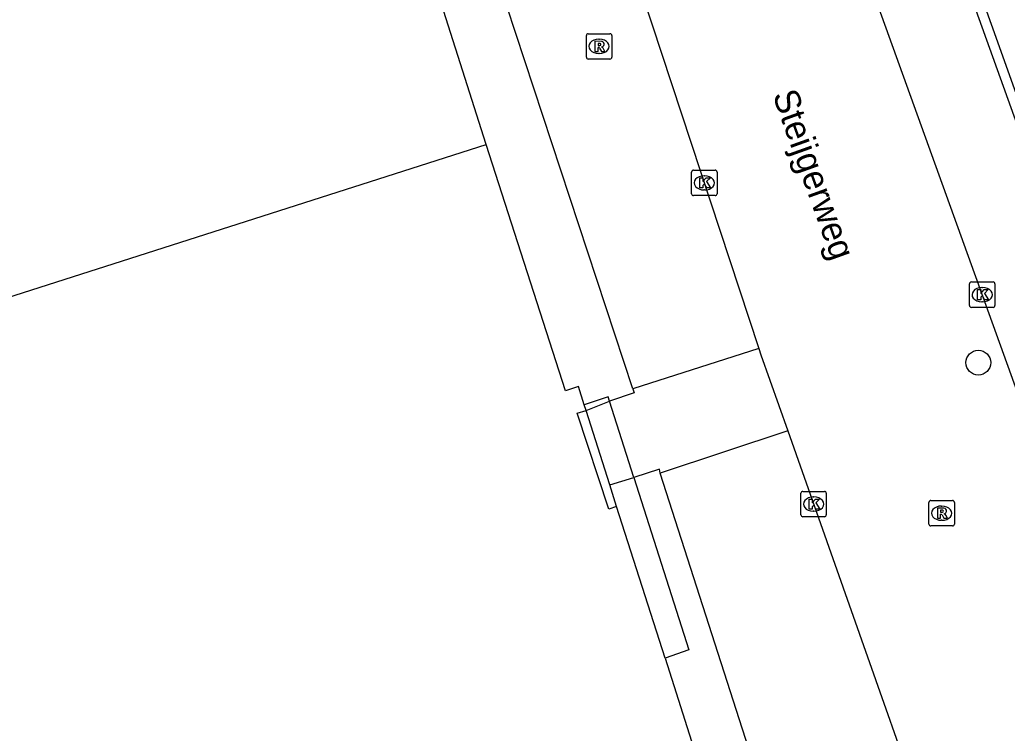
# Model space of a CAD drawing. Extents: x 159503 to 160347, y 382525 to 383272.
# Drawn here: x 159552.91 to 159591.78, y 382930.55 to 382958.63 of the extents above; entities that cross this region are included whole.
import ezdxf

# ---------------------------------------------------------------- set-up
doc = ezdxf.new("R2010")
doc.units = 0
for name, color, linetype in [('IMGEO_Boom', 7, 'Continuous'), ('IMGEO_Kolk', 7, 'Continuous'), ('IMGEO_Openbare_ruimte_label', 7, 'Continuous'), ('IMGEO_Pand', 7, 'Continuous'), ('IMGEO_Rijbaan_lokaal_open', 7, 'Continuous'), ('IMGEO_Rioolput', 7, 'Continuous'), ('IMGEO_Voetpad_open', 7, 'Continuous')]:
    doc.layers.add(name, color=color, linetype=linetype)

msp = doc.modelspace()

# ---------------------------------------------------------------- linework, layer by layer
at = {"layer": 'IMGEO_Boom'}
msp.add_circle((159590.637, 382945.135), 0.489, dxfattribs=at)
at = {"layer": 'IMGEO_Kolk'}
for p, q in [((159579.353, 382951.785), (159579.353, 382952.637)), ((159579.428, 382952.711), (159580.28, 382952.711)), ((159579.841, 382952.491), (159579.866, 382952.491)), ((159580.354, 382952.637), (159580.354, 382951.785)), ((159580.28, 382951.711), (159579.428, 382951.711)), ((159579.864, 382951.931), (159579.839, 382951.931)), ((159590.289, 382947.385), (159590.289, 382948.237)), ((159590.364, 382948.311), (159591.216, 382948.311)), ((159591.29, 382948.237), (159591.29, 382947.385)), ((159590.777, 382948.091), (159590.802, 382948.091)), ((159590.8, 382947.531), (159590.775, 382947.531)), ((159591.216, 382947.311), (159590.364, 382947.311)), ((159583.729, 382940.068), (159584.581, 382940.068)), ((159583.654, 382939.142), (159583.654, 382939.994)), ((159584.142, 382939.848), (159584.167, 382939.848)), ((159584.655, 382939.994), (159584.655, 382939.142)), ((159584.165, 382939.288), (159584.14, 382939.288)), ((159584.581, 382939.068), (159583.729, 382939.068))]:
    msp.add_line(p, q, dxfattribs=at)
for points in [[(159579.353, 382951.785), (159579.353, 382952.637)], [(159579.428, 382952.711), (159580.28, 382952.711)], [(159580.354, 382952.637), (159580.354, 382951.785)], [(159579.674, 382952.411), (159579.797, 382952.411), (159579.797, 382952.26), (159579.927, 382952.411), (159580.091, 382952.411), (159579.945, 382952.26), (159580.098, 382952.011), (159579.946, 382952.011), (159579.861, 382952.175), (159579.797, 382952.108), (159579.797, 382952.011), (159579.674, 382952.011), (159579.674, 382952.411)], [(159580.28, 382951.711), (159579.428, 382951.711)], [(159590.289, 382947.385), (159590.289, 382948.237)], [(159590.364, 382948.311), (159591.216, 382948.311)], [(159591.29, 382948.237), (159591.29, 382947.385)], [(159590.61, 382948.011), (159590.733, 382948.011), (159590.733, 382947.86), (159590.863, 382948.011), (159591.027, 382948.011), (159590.881, 382947.86), (159591.034, 382947.611), (159590.882, 382947.611), (159590.797, 382947.775), (159590.733, 382947.708), (159590.733, 382947.611), (159590.61, 382947.611), (159590.61, 382948.011)], [(159591.216, 382947.311), (159590.364, 382947.311)], [(159583.729, 382940.068), (159584.581, 382940.068)], [(159583.654, 382939.142), (159583.654, 382939.994)], [(159583.975, 382939.768), (159584.098, 382939.768), (159584.098, 382939.617), (159584.228, 382939.768), (159584.392, 382939.768), (159584.246, 382939.617), (159584.399, 382939.368), (159584.247, 382939.368), (159584.162, 382939.532), (159584.098, 382939.465), (159584.098, 382939.368), (159583.975, 382939.368), (159583.975, 382939.768)], [(159584.655, 382939.994), (159584.655, 382939.142)], [(159584.581, 382939.068), (159583.729, 382939.068)]]:
    msp.add_lwpolyline(points, dxfattribs=at)
for centre, start, end in [((159579.43, 382952.635), 91.552, 178.448), ((159579.43, 382952.635), 91.552, 178.448), ((159580.278, 382952.635), 1.552, 88.448), ((159580.278, 382952.635), 1.552, 88.448), ((159579.43, 382951.787), 181.552, 268.448), ((159579.43, 382951.787), 181.552, 268.448), ((159580.278, 382951.787), 271.552, 358.448), ((159580.278, 382951.787), 271.552, 358.448), ((159590.366, 382948.235), 91.552, 178.448), ((159590.366, 382948.235), 91.552, 178.448), ((159591.214, 382948.235), 1.552, 88.448), ((159591.214, 382948.235), 1.552, 88.448), ((159590.366, 382947.387), 181.552, 268.448), ((159590.366, 382947.387), 181.552, 268.448), ((159591.214, 382947.387), 271.552, 358.448), ((159591.214, 382947.387), 271.552, 358.448), ((159583.731, 382939.992), 91.552, 178.448), ((159583.731, 382939.992), 91.552, 178.448), ((159584.579, 382939.992), 1.552, 88.448), ((159584.579, 382939.992), 1.552, 88.448), ((159583.731, 382939.144), 181.552, 268.448), ((159583.731, 382939.144), 181.552, 268.448), ((159584.579, 382939.144), 271.552, 358.448), ((159584.579, 382939.144), 271.552, 358.448)]:
    msp.add_arc(centre, 0.0765, start, end, dxfattribs=at)
for centre, major_axis, ratio, start_param, end_param in [((159579.84, 382952.211), (-0.387, 0.002), 0.722429, 4.712389, 7.853982), ((159579.865, 382952.211), (-0.39, 0.002), 0.717154, 1.570796, 4.712389), ((159590.776, 382947.811), (-0.387, 0.002), 0.722429, 4.712389, 7.853982), ((159590.801, 382947.811), (-0.39, 0.002), 0.717154, 1.570796, 4.712389), ((159584.141, 382939.568), (-0.387, 0.002), 0.722429, 4.712389, 7.853982), ((159584.166, 382939.568), (-0.39, 0.002), 0.717154, 1.570796, 4.712389)]:
    msp.add_ellipse(centre, major_axis=major_axis, ratio=ratio, start_param=start_param, end_param=end_param, dxfattribs=at)
at = {"layer": 'IMGEO_Pand'}
for points in [[(159587.852, 382966.52), (159588.22, 382966.653), (159594.075, 382950.274)], [(159571.265, 382953.723), (159568.852, 382961.323)], [(159545.874, 382945.595), (159571.265, 382953.723)], [(159575.129, 382943.477), (159574.901, 382944.198), (159574.389, 382944.03), (159571.265, 382953.723)], [(159576.401, 382939.467), (159576.097, 382939.369), (159574.851, 382943.147), (159575.2, 382943.254)], [(159575.2, 382943.254), (159575.129, 382943.477)], [(159578.31, 382933.501), (159576.401, 382939.467)], [(159578.31, 382933.501), (159579.526, 382929.703), (159579.035, 382929.541), (159582.89, 382917.624)]]:
    msp.add_lwpolyline(points, dxfattribs=at)
at = {"layer": 'IMGEO_Rijbaan_lokaal_open'}
for points in [[(159575.122, 382966.572), (159582.001, 382945.695)], [(159584.573, 382965.063), (159592.904, 382941.945)], [(159582.001, 382945.695), (159582.084, 382945.442), (159583.137, 382942.457)], [(159583.137, 382942.457), (159591.263, 382919.413)]]:
    msp.add_lwpolyline(points, dxfattribs=at)
at = {"layer": 'IMGEO_Rioolput'}
for p, q in [((159575.212, 382957.157), (159575.212, 382958.009)), ((159575.287, 382958.083), (159576.139, 382958.083)), ((159576.213, 382958.009), (159576.213, 382957.157)), ((159575.7, 382957.863), (159575.725, 382957.863)), ((159575.723, 382957.303), (159575.698, 382957.303)), ((159576.139, 382957.083), (159575.287, 382957.083)), ((159588.693, 382938.784), (159588.693, 382939.636)), ((159588.768, 382939.71), (159589.62, 382939.71)), ((159589.694, 382939.636), (159589.694, 382938.784)), ((159589.181, 382939.49), (159589.206, 382939.49)), ((159589.204, 382938.93), (159589.179, 382938.93)), ((159589.62, 382938.71), (159588.768, 382938.71))]:
    msp.add_line(p, q, dxfattribs=at)
for points in [[(159575.212, 382957.157), (159575.212, 382958.009)], [(159575.287, 382958.083), (159576.139, 382958.083)], [(159576.213, 382958.009), (159576.213, 382957.157)], [(159575.801, 382957.781), (159575.549, 382957.783), (159575.549, 382957.383)], [(159575.549, 382957.383), (159575.673, 382957.383), (159575.673, 382957.545), (159575.684, 382957.545)], [(159575.727, 382957.702), (159575.673, 382957.702), (159575.673, 382957.621)], [(159575.673, 382957.621), (159575.725, 382957.621)], [(159575.731, 382957.516), (159575.802, 382957.383), (159575.942, 382957.383), (159575.877, 382957.509)], [(159576.139, 382957.083), (159575.287, 382957.083)], [(159588.693, 382938.784), (159588.693, 382939.636)], [(159588.768, 382939.71), (159589.62, 382939.71)], [(159589.694, 382939.636), (159589.694, 382938.784)], [(159589.282, 382939.408), (159589.03, 382939.41), (159589.03, 382939.01)], [(159589.208, 382939.329), (159589.154, 382939.329), (159589.154, 382939.248)], [(159589.154, 382939.248), (159589.206, 382939.248)], [(159589.03, 382939.01), (159589.154, 382939.01), (159589.154, 382939.172), (159589.165, 382939.172)], [(159589.212, 382939.143), (159589.283, 382939.01), (159589.423, 382939.01), (159589.358, 382939.136)], [(159589.62, 382938.71), (159588.768, 382938.71)]]:
    msp.add_lwpolyline(points, dxfattribs=at)
for centre, radius, start, end in [((159575.289, 382958.007), 0.0765, 91.552, 178.448), ((159575.289, 382958.007), 0.0765, 91.552, 178.448), ((159576.137, 382958.007), 0.0765, 1.552, 88.448), ((159576.137, 382958.007), 0.0765, 1.552, 88.448), ((159575.683, 382957.492), 0.0533, 26.0293, 88.6989), ((159575.709, 382957.81), 0.19, 274.7715, 282.9687), ((159575.733, 382957.606), 0.0964, 77.0061, 93.1865), ((159575.747, 382957.663), 0.0378, 276.6634, 79.6772), ((159575.8, 382957.671), 0.109, 350.3612, 89.416), ((159575.798, 382957.671), 0.112, 277.5842, 350.9817), ((159575.782, 382957.456), 0.108, 29.5134, 73.7905), ((159575.289, 382957.159), 0.0765, 181.552, 268.448), ((159575.289, 382957.159), 0.0765, 181.552, 268.448), ((159576.137, 382957.159), 0.0765, 271.552, 358.448), ((159576.137, 382957.159), 0.0765, 271.552, 358.448), ((159588.77, 382939.634), 0.0765, 91.552, 178.448), ((159588.77, 382939.634), 0.0765, 91.552, 178.448), ((159589.618, 382939.634), 0.0765, 1.552, 88.448), ((159589.618, 382939.634), 0.0765, 1.552, 88.448), ((159589.19, 382939.437), 0.19, 274.7715, 282.9687), ((159589.214, 382939.233), 0.0964, 77.0061, 93.1865), ((159589.228, 382939.29), 0.0378, 276.6634, 79.6772), ((159589.281, 382939.298), 0.109, 350.3612, 89.416), ((159589.279, 382939.298), 0.112, 277.5842, 350.9817), ((159589.164, 382939.119), 0.0533, 26.0293, 88.6989), ((159589.263, 382939.083), 0.108, 29.5134, 73.7905), ((159588.77, 382938.786), 0.0765, 181.552, 268.448), ((159588.77, 382938.786), 0.0765, 181.552, 268.448), ((159589.618, 382938.786), 0.0765, 271.552, 358.448), ((159589.618, 382938.786), 0.0765, 271.552, 358.448)]:
    msp.add_arc(centre, radius, start, end, dxfattribs=at)
for centre, major_axis, ratio, start_param, end_param in [((159575.699, 382957.583), (-0.387, 0.002), 0.722429, 4.712389, 7.853982), ((159575.724, 382957.583), (-0.39, 0.002), 0.717154, 1.570796, 4.712389), ((159589.18, 382939.21), (-0.387, 0.002), 0.722429, 4.712389, 7.853982), ((159589.205, 382939.21), (-0.39, 0.002), 0.717154, 1.570796, 4.712389)]:
    msp.add_ellipse(centre, major_axis=major_axis, ratio=ratio, start_param=start_param, end_param=end_param, dxfattribs=at)
at = {"layer": 'IMGEO_Voetpad_open'}
for points in [[(159577.04, 382944.103), (159571.02, 382962.408), (159567.304, 382974.008), (159572.292, 382975.496)], [(159595.17, 382946.154), (159587.852, 382966.52)], [(159582.001, 382945.695), (159577.04, 382944.103)], [(159577.04, 382944.103), (159577.091, 382943.948), (159576.117, 382943.621)], [(159576.117, 382943.621), (159576.065, 382943.784), (159575.129, 382943.477)], [(159575.2, 382943.254), (159576.117, 382943.621)], [(159577.077, 382940.619), (159576.117, 382943.621)], [(159576.141, 382940.323), (159575.2, 382943.254)], [(159583.137, 382942.457), (159578.122, 382940.788)], [(159578.122, 382940.788), (159578.083, 382940.937), (159577.077, 382940.619)], [(159576.141, 382940.323), (159577.077, 382940.619)], [(159577.077, 382940.619), (159579.249, 382933.828), (159578.31, 382933.501)], [(159590.597, 382919.659), (159585.433, 382918.024), (159578.122, 382940.788)], [(159576.401, 382939.467), (159576.141, 382940.323)]]:
    msp.add_lwpolyline(points, dxfattribs=at)

# ---------------------------------------------------------------- texts
at = {"layer": 'IMGEO_Openbare_ruimte_label'}
msp.add_text('Steijgerweg', height=1, rotation=289.704, dxfattribs=at).set_placement((159582.529, 382955.674))

doc.saveas('drawing.dxf')
